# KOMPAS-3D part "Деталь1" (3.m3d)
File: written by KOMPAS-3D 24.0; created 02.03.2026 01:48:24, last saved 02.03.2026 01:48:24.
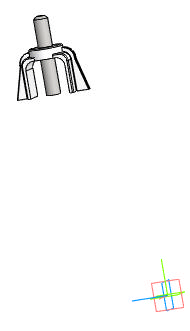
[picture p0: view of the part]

Document properties: Автор: R2D2; Полное имя файла: E:\Работа\Зайцев\GVWR3131M-2W-F-S Задвижка клиновая с выдвижным штоком DN.ru Ду50-200 Ру63\DN150\исходные материалы\3.m3d

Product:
- Body: Твердое тело1  | qty 1
    Масса: 1.47915
- Part/product: Деталь1
    Масса: 1.47915
    additional columns: Типовые

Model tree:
1. Твердое тело1  (labels: Твердое тело1)
2. Эскиз:1
3. Элемент выдавливания:1
     Расстояние 1 = 500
